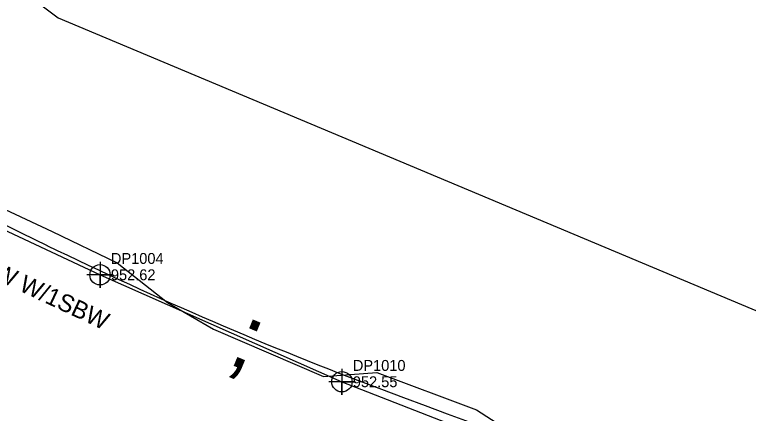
# Model space of a CAD drawing. Extents: x 1182322 to 1186765, y 572295 to 575411.
# Drawn here: x 1185300.8 to 1185469.1, y 574007 to 574098.5 of the extents above; entities that cross this region are included whole.
import ezdxf

# ---------------------------------------------------------------- set-up
doc = ezdxf.new("R2010")
doc.units = 0
for name, color, linetype in [('Exist Other Culture Fence Line', 7, 'Continuous'), ('Exist Other Culture Fence Line Cogo Elevation', 7, 'Continuous'), ('Exist Other Culture Fence Line Cogo Number', 7, 'Continuous'), ('Exist Other Culture Fence Line Cogo Point CELL', 7, 'Continuous'), ('Exist Other Culture Fence Line Text', 7, 'Continuous'), ('Exist Right of Way Control of Access CA Symbol CELL', 7, 'Continuous'), ('Exist Right of Way Line', 7, 'Continuous'), ('Exist Vegetation Woods Line', 7, 'Continuous'), ('Sheet Layout Plan Border', 7, 'Continuous')]:
    doc.layers.add(name, color=color, linetype=linetype)

msp = doc.modelspace()

# ---------------------------------------------------------------- linework, layer by layer
at = {"layer": 'Exist Other Culture Fence Line'}
msp.add_lwpolyline([(1184859.89, 574383.59), (1184869.68, 574315.09), (1184908.6, 574288.34), (1184956.03, 574255.54), (1185009.07, 574217.02), (1185046.56, 574193.02), (1185093.48, 574162.62), (1185152.72, 574124.64), (1185217.54, 574090.13), (1185270.37, 574062.3), (1185320.4, 574038.84), (1185375.89, 574014.29), (1185431.73, 573992.44), (1185491.11, 573971.52), (1185538.71, 573956.46), (1185576.16, 573944.72), (1185627.61, 573931.32)], dxfattribs=at)
at = {"layer": 'Exist Other Culture Fence Line Cogo Point CELL'}
for points in [[(1185320.4, 574041.84), (1185320.4, 574035.84), (1185320.4, 574038.84), (1185323.4, 574038.84), (1185317.4, 574038.84)], [(1185375.89, 574017.29), (1185375.89, 574011.29), (1185375.89, 574014.29), (1185378.89, 574014.29), (1185372.89, 574014.29)]]:
    msp.add_lwpolyline(points, dxfattribs=at)
for centre in [(1185320.4, 574038.84), (1185375.89, 574014.29)]:
    msp.add_circle(centre, 2.34, dxfattribs=at)
at = {"layer": 'Exist Right of Way Control of Access CA Symbol CELL'}
msp.add_line((1185359.13, 574022.73), (1185359.13, 574022.73), dxfattribs=at)
at = {"layer": 'Exist Right of Way Line'}
for centre, radius, start, end in [((1186843.72, 577198.3), 3506.76, 242.3123, 244.03246), ((1185699.1, 574848.11), 892.65, 244.03246, 249.39538), ((1186394.82, 576698.6), 2869.6, 249.39538, 256.24258)]:
    msp.add_arc(centre, radius, start, end, dxfattribs=at)
at = {"layer": 'Exist Vegetation Woods Line'}
msp.add_lwpolyline([(1185285.21, 574060.08), (1185309.44, 574048.8), (1185324.32, 574041.57), (1185335.88, 574032.48), (1185346.42, 574026.39), (1185371.67, 574015.48), (1185383.93, 574016.42), (1185406.75, 574007.88), (1185431.09, 573992.16), (1185441.34, 573990.08), (1185450.82, 573991.25), (1185462.07, 573988.89), (1185487.68, 573978.75), (1185499.33, 573972.48), (1185515.21, 573971.52), (1185535.92, 573963.33), (1185546.48, 573961.63), (1185564.05, 573955.41), (1185572.33, 573948.02)], dxfattribs=at)
at = {"layer": 'Sheet Layout Plan Border'}
msp.add_lwpolyline([(1185081.81, 574269.31), (1185310.78, 574097.8), (1185590.56, 573980.35)], dxfattribs=at)

# ---------------------------------------------------------------- texts
at = {"layer": 'Exist Other Culture Fence Line Cogo Elevation'}
for s, p in [('952.62', (1185322.9, 574037.59)), ('952.55', (1185378.39, 574013.04))]:
    msp.add_text(s, height=2.5, dxfattribs=at).set_placement(p)
at = {"layer": 'Exist Other Culture Fence Line Cogo Number'}
for s, p in [('DP1004', (1185322.9, 574041.34)), ('DP1010', (1185378.39, 574016.79))]:
    msp.add_text(s, height=2.5, dxfattribs=at).set_placement(p)
at = {"layer": 'Exist Other Culture Fence Line Text'}
msp.add_text('48" WW W/1SBW', height=4, rotation=334.88, dxfattribs=at).set_placement((1185282.66, 574044.19))
at = {"layer": 'Exist Right of Way Control of Access CA Symbol CELL'}
msp.add_text(';', height=15, rotation=337.6138, dxfattribs=at).set_placement((1185349.34, 574018.65))

doc.saveas('drawing.dxf')
